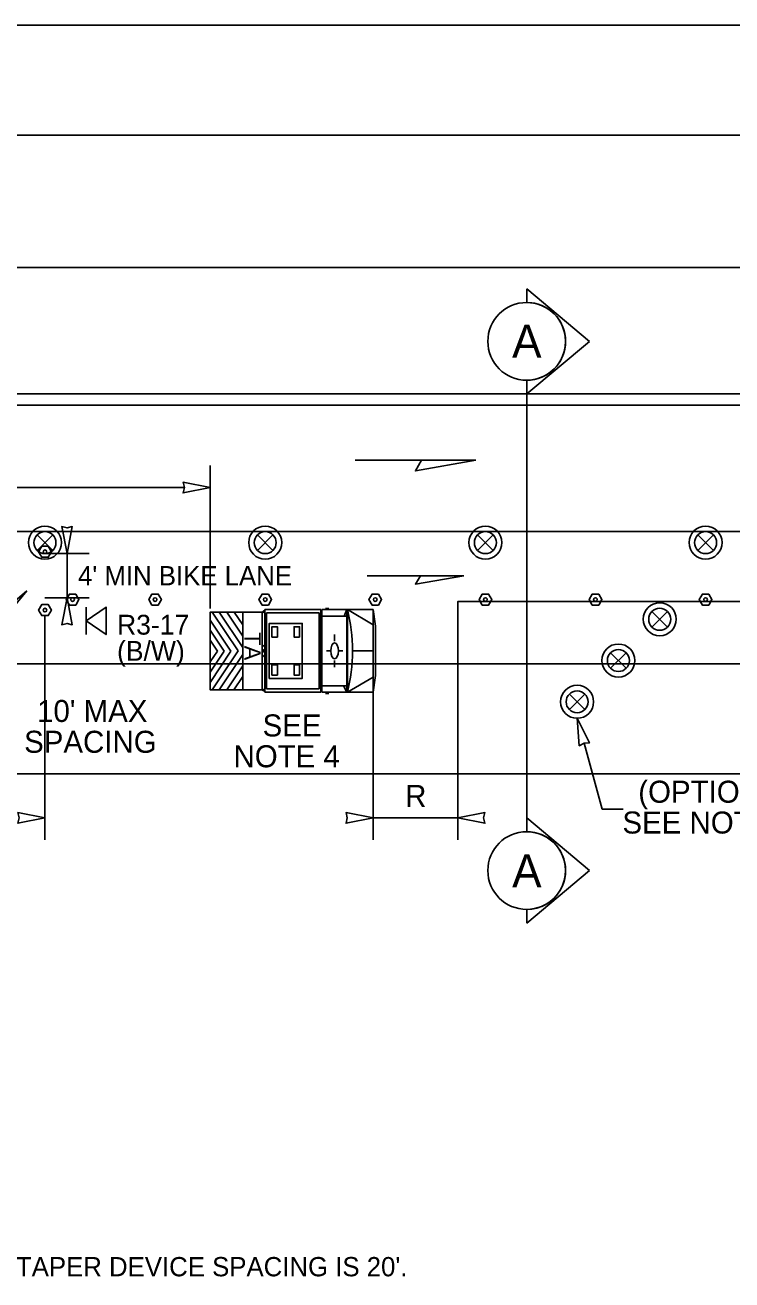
# Model space of a CAD drawing. Extents: x 99958 to 100176, y 99935 to 100011.
# Drawn here: x 100008.891 to 100011.459, y 99942.898 to 99947.456 of the extents above; entities that cross this region are included whole.
import ezdxf

# ---------------------------------------------------------------- set-up
doc = ezdxf.new("R2010")
doc.units = 0
for name, color, linetype in [('RD_ED_ShoulderPavedEdge', 7, 'Continuous'), ('RD_MK_LineDblYellowCenter', 7, 'Continuous'), ('RD_MK_LineEdgeWhite', 7, 'Continuous'), ('RD_MK_LineLane', 7, 'Continuous'), ('SH_GI_GeneralNotesBodyText', 7, 'Continuous'), ('SH_TI_WZSectionCut', 7, 'Continuous'), ('TR_SN_ConstructionSigns', 7, 'Continuous'), ('TR_WZ_PortableSignMountBlk-Wht', 7, 'Continuous'), ('TR_WZ_TrafficSafetyDrum', 7, 'Continuous'), ('TR_WZ_TransportableAttenuator', 7, 'Continuous'), ('TR_WZ_TubularMarker', 7, 'Continuous'), ('TR_WZ_WorkZoneDetails', 7, 'Continuous'), ('TR_WZ_WorkZoneTextCurrent', 7, 'Continuous')]:
    doc.layers.add(name, color=color, linetype=linetype)

msp = doc.modelspace()

# ---------------------------------------------------------------- linework, layer by layer
at = {"layer": 'RD_ED_ShoulderPavedEdge'}
for p, q in [((100000.8283, 99947.4557), (100014.8933, 99947.4557)), ((100000.8283, 99944.7357), (100014.8933, 99944.7357))]:
    msp.add_line(p, q, dxfattribs=at)
at = {"layer": 'RD_MK_LineDblYellowCenter'}
for p, q in [((100000.8283, 99946.1157), (100014.914, 99946.1157)), ((100000.8283, 99946.0757), (100014.8726, 99946.0757))]:
    msp.add_line(p, q, dxfattribs=at)
at = {"layer": 'RD_MK_LineEdgeWhite'}
for p, q in [((100000.8283, 99947.0557), (100014.8933, 99947.0557)), ((100000.8283, 99945.1357), (100014.8933, 99945.1357))]:
    msp.add_line(p, q, dxfattribs=at)
at = {"layer": 'RD_MK_LineLane'}
for points in [[(100014.8933, 99946.5757), (100000.8283, 99946.5757)], [(100014.8933, 99945.6157), (100000.8283, 99945.6157)]]:
    msp.add_lwpolyline(points, dxfattribs=at)
at = {"layer": 'SH_TI_WZSectionCut'}
for p, q in [((100010.7136, 99946.4481), (100010.7136, 99946.498)), ((100010.7136, 99946.498), (100010.9417, 99946.3069)), ((100010.9417, 99946.3069), (100010.7136, 99946.1157)), ((100010.7136, 99946.1157), (100010.7136, 99946.1656)), ((100010.7136, 99946.1157), (100010.7136, 99944.5757)), ((100010.7136, 99944.5757), (100010.7136, 99944.5258)), ((100010.9417, 99944.3846), (100010.7136, 99944.5757)), ((100010.7136, 99944.1935), (100010.9417, 99944.3846)), ((100010.7136, 99944.2434), (100010.7136, 99944.1935))]:
    msp.add_line(p, q, dxfattribs=at)
for centre in [(100010.7136, 99946.3069), (100010.7136, 99944.3846)]:
    msp.add_circle(centre, 0.1412, dxfattribs=at)
for centre in [(100010.7136, 99946.3069), (100010.7136, 99944.3846)]:
    msp.add_arc(centre, 0.1412, 269.9978, 90.0022, dxfattribs=at)
at = {"layer": 'TR_WZ_PortableSignMountBlk-Wht'}
msp.add_line((100009.1136, 99945.2416), (100009.1136, 99945.3416), dxfattribs=at)
msp.add_lwpolyline([(100009.1136, 99945.2916), (100009.1854, 99945.3416), (100009.1854, 99945.2416)], close=True, dxfattribs=at)
at = {"layer": 'TR_WZ_TrafficSafetyDrum'}
for p, q in [((100008.9353, 99945.604), (100008.9919, 99945.5474)), ((100008.9919, 99945.604), (100008.9353, 99945.5474)), ((100008.9353, 99945.604), (100008.9919, 99945.5474)), ((100008.9919, 99945.604), (100008.9353, 99945.5474)), ((100009.7353, 99945.604), (100009.7919, 99945.5474)), ((100009.7919, 99945.604), (100009.7353, 99945.5474)), ((100009.7353, 99945.604), (100009.7919, 99945.5474)), ((100009.7919, 99945.604), (100009.7353, 99945.5474)), ((100010.5353, 99945.604), (100010.5919, 99945.5474)), ((100010.5919, 99945.604), (100010.5353, 99945.5474)), ((100010.5353, 99945.604), (100010.5919, 99945.5474)), ((100010.5919, 99945.604), (100010.5353, 99945.5474)), ((100011.3353, 99945.604), (100011.3919, 99945.5474)), ((100011.3919, 99945.604), (100011.3353, 99945.5474)), ((100011.3353, 99945.604), (100011.3919, 99945.5474)), ((100011.3919, 99945.604), (100011.3353, 99945.5474)), ((100011.2252, 99945.2692), (100011.1686, 99945.3257)), ((100011.1686, 99945.2692), (100011.2252, 99945.3257)), ((100011.0752, 99945.1192), (100011.0186, 99945.1757)), ((100011.0186, 99945.1192), (100011.0752, 99945.1757)), ((100010.9252, 99944.9692), (100010.8686, 99945.0257)), ((100010.8686, 99944.9692), (100010.9252, 99945.0257))]:
    msp.add_line(p, q, dxfattribs=at)
for centre, radius in [((100008.9636, 99945.5757), 0.06), ((100008.9636, 99945.5757), 0.06), ((100008.9636, 99945.5757), 0.06), ((100008.9636, 99945.5757), 0.06), ((100008.9636, 99945.5757), 0.04), ((100008.9636, 99945.5757), 0.04), ((100009.7636, 99945.5757), 0.06), ((100009.7636, 99945.5757), 0.06), ((100009.7636, 99945.5757), 0.06), ((100009.7636, 99945.5757), 0.06), ((100009.7636, 99945.5757), 0.04), ((100009.7636, 99945.5757), 0.04), ((100010.5636, 99945.5757), 0.06), ((100010.5636, 99945.5757), 0.06), ((100010.5636, 99945.5757), 0.06), ((100010.5636, 99945.5757), 0.06), ((100010.5636, 99945.5757), 0.04), ((100010.5636, 99945.5757), 0.04), ((100011.3636, 99945.5757), 0.06), ((100011.3636, 99945.5757), 0.06), ((100011.3636, 99945.5757), 0.06), ((100011.3636, 99945.5757), 0.06), ((100011.3636, 99945.5757), 0.04), ((100011.3636, 99945.5757), 0.04), ((100011.1969, 99945.2975), 0.06), ((100011.1969, 99945.2975), 0.06), ((100011.1969, 99945.2975), 0.04), ((100011.0469, 99945.1475), 0.06), ((100011.0469, 99945.1475), 0.06), ((100011.0469, 99945.1475), 0.04), ((100010.8969, 99944.9975), 0.06), ((100010.8969, 99944.9975), 0.06), ((100010.8969, 99944.9975), 0.04)]:
    msp.add_circle(centre, radius, dxfattribs=at)
at = {"layer": 'TR_WZ_TransportableAttenuator'}
for p, q in [((100009.5965, 99945.3231), (100009.5713, 99945.3231)), ((100009.5713, 99945.3231), (100009.6651, 99945.1821)), ((100009.6651, 99945.1821), (100009.5713, 99945.3231)), ((100009.5713, 99945.3231), (100009.5965, 99945.3231)), ((100009.6818, 99945.1948), (100009.5965, 99945.3231)), ((100009.5965, 99945.3231), (100009.6818, 99945.1948)), ((100009.651, 99945.3231), (100009.624, 99945.3231)), ((100009.624, 99945.3231), (100009.6818, 99945.2363)), ((100009.6818, 99945.2363), (100009.624, 99945.3231)), ((100009.624, 99945.3231), (100009.651, 99945.3231)), ((100009.6818, 99945.2777), (100009.651, 99945.3231)), ((100009.651, 99945.3231), (100009.6818, 99945.2777)), ((100009.7625, 99945.3229), (100009.6818, 99945.3229)), ((100009.6818, 99945.3229), (100009.6818, 99945.0413)), ((100009.7529, 99945.0465), (100009.7529, 99945.3183)), ((100009.7574, 99945.3275), (100009.7618, 99945.3275)), ((100009.7618, 99945.0373), (100009.7618, 99945.3275)), ((100009.7625, 99945.3324), (100009.966, 99945.3324)), ((100009.7625, 99945.0324), (100009.7625, 99945.3324)), ((100009.7625, 99945.0418), (100009.7625, 99945.3229)), ((100009.7683, 99945.0444), (100009.7683, 99945.3204)), ((100009.7683, 99945.3204), (100009.9603, 99945.3204)), ((100009.9603, 99945.0444), (100009.9603, 99945.3204)), ((100009.966, 99945.0324), (100009.966, 99945.3324)), ((100009.9688, 99945.0324), (100009.9688, 99945.3324)), ((100010.1557, 99945.3324), (100009.9688, 99945.3324)), ((100009.9943, 99945.3366), (100009.983, 99945.3366)), ((100010.0507, 99945.3092), (100010.0606, 99945.3324)), ((100010.0606, 99945.0324), (100010.0606, 99945.3324)), ((100010.0622, 99945.0324), (100010.0622, 99945.3324)), ((100010.1557, 99945.2775), (100010.0622, 99945.3324)), ((100010.1557, 99945.0324), (100010.1557, 99945.3324)), ((100010.1557, 99945.3324), (100010.1649, 99945.2718)), ((100009.6389, 99945.1813), (100009.5636, 99945.2945)), ((100009.5636, 99945.2945), (100009.5636, 99945.2577)), ((100009.5636, 99945.2577), (100009.5636, 99945.2945)), ((100009.5636, 99945.2945), (100009.6389, 99945.1813)), ((100009.6818, 99945.2363), (100009.6818, 99945.2777)), ((100009.6818, 99945.2777), (100009.6818, 99945.2363)), ((100010.0606, 99945.3092), (100009.9688, 99945.3092)), ((100010.1649, 99945.093), (100010.1649, 99945.2718)), ((100009.5636, 99945.2577), (100009.6147, 99945.1809)), ((100009.6147, 99945.1809), (100009.5636, 99945.2577)), ((100010.0157, 99945.2419), (100010.0157, 99945.2176)), ((100009.5898, 99945.182), (100009.5636, 99945.2212)), ((100009.5636, 99945.2212), (100009.5636, 99945.1432)), ((100009.5636, 99945.2212), (100009.5898, 99945.182)), ((100009.5636, 99945.1432), (100009.5636, 99945.2212)), ((100009.5636, 99945.1432), (100009.5898, 99945.182)), ((100009.5898, 99945.182), (100009.5636, 99945.1432)), ((100009.5636, 99945.0681), (100009.6389, 99945.1813)), ((100009.6389, 99945.1813), (100009.5636, 99945.0681)), ((100009.6147, 99945.1809), (100009.5636, 99945.1046)), ((100009.5636, 99945.1046), (100009.6147, 99945.1809)), ((100009.6651, 99945.1821), (100009.5714, 99945.0413)), ((100009.5714, 99945.0413), (100009.6651, 99945.1821)), ((100009.6818, 99945.1697), (100009.6818, 99945.1948)), ((100009.6818, 99945.1948), (100009.6818, 99945.1697)), ((100009.7529, 99945.2036), (100009.7618, 99945.1979)), ((100009.7553, 99945.1824), (100009.7594, 99945.1824)), ((100009.7574, 99945.1782), (100009.7574, 99945.1866)), ((100009.9858, 99945.1822), (100009.9983, 99945.1823)), ((100010.0017, 99945.1829), (100010.0017, 99945.1829)), ((100010.0455, 99945.1822), (100010.033, 99945.1823)), ((100010.1557, 99945.1824), (100010.0806, 99945.1824)), ((100009.597, 99945.0413), (100009.6818, 99945.1697)), ((100009.6818, 99945.1697), (100009.597, 99945.0413)), ((100009.7529, 99945.1613), (100009.7618, 99945.1669)), ((100010.0157, 99945.123), (100010.0157, 99945.1472)), ((100009.5636, 99945.1046), (100009.5636, 99945.0681)), ((100009.5636, 99945.0681), (100009.5636, 99945.1046)), ((100009.6818, 99945.1282), (100009.6247, 99945.0413)), ((100009.6247, 99945.0413), (100009.6818, 99945.1282)), ((100009.6502, 99945.0413), (100009.6818, 99945.089)), ((100009.6818, 99945.089), (100009.6502, 99945.0413)), ((100009.6818, 99945.089), (100009.6818, 99945.1282)), ((100009.6818, 99945.1282), (100009.6818, 99945.089)), ((100010.1557, 99945.0324), (100010.1649, 99945.093)), ((100009.7683, 99945.0444), (100009.9603, 99945.0444)), ((100010.0606, 99945.0557), (100009.9688, 99945.0557)), ((100010.0606, 99945.0324), (100010.0486, 99945.0557)), ((100010.1557, 99945.0874), (100010.0622, 99945.0324)), ((100009.5714, 99945.0413), (100009.597, 99945.0413)), ((100009.597, 99945.0413), (100009.5714, 99945.0413)), ((100009.6247, 99945.0413), (100009.6502, 99945.0413)), ((100009.6502, 99945.0413), (100009.6247, 99945.0413)), ((100009.7625, 99945.0413), (100009.6818, 99945.0413)), ((100009.7574, 99945.0373), (100009.7618, 99945.0373)), ((100009.7625, 99945.0324), (100009.966, 99945.0324)), ((100010.1557, 99945.0324), (100009.9688, 99945.0324)), ((100009.9943, 99945.0282), (100009.983, 99945.0282))]:
    msp.add_line(p, q, dxfattribs=at)
for points in [[(100009.6818, 99945.3231), (100009.5636, 99945.3231), (100009.5636, 99945.0413), (100009.6818, 99945.0413)], [(100009.7783, 99945.0824), (100009.8985, 99945.0824), (100009.8985, 99945.2824), (100009.7783, 99945.2824)], [(100009.7883, 99945.2324), (100009.8083, 99945.2324), (100009.8083, 99945.2699), (100009.7883, 99945.2699)], [(100009.8885, 99945.2324), (100009.8685, 99945.2324), (100009.8685, 99945.2699), (100009.8885, 99945.2699)], [(100009.7883, 99945.0949), (100009.8083, 99945.0949), (100009.8083, 99945.1324), (100009.7883, 99945.1324)], [(100009.8885, 99945.0949), (100009.8685, 99945.0949), (100009.8685, 99945.1324), (100009.8885, 99945.1324)]]:
    msp.add_lwpolyline(points, close=True, dxfattribs=at)
msp.add_lwpolyline([(100009.6818, 99945.0413), (100009.5636, 99945.0413), (100009.5636, 99945.3231), (100009.6818, 99945.3229)], dxfattribs=at)
for centre, major_axis, start_param, end_param in [((100009.7574, 99945.3183), (0, 0.00916), 0, 1.570796), ((100009.9287, 99945.1824), (0, 0.3148), 4.215667, 5.208926), ((100009.7574, 99945.0465), (0, -0.00916), 4.712389, 6.283185)]:
    msp.add_ellipse(centre, major_axis=major_axis, ratio=0.482618, start_param=start_param, end_param=end_param, dxfattribs=at)
for centre, major_axis in [((100009.7574, 99945.1824), (0, -0.00423)), ((100010.0157, 99945.1824), (0, -0.0289))]:
    msp.add_ellipse(centre, major_axis=major_axis, ratio=0.482618, dxfattribs=at)
at = {"layer": 'TR_WZ_TubularMarker'}
for points in [[(100008.9405, 99945.5424), (100008.9521, 99945.5624), (100008.9752, 99945.5624), (100008.9867, 99945.5424), (100008.9752, 99945.5224), (100008.9521, 99945.5224)], [(100009.0405, 99945.3691), (100009.0521, 99945.3891), (100009.0752, 99945.3891), (100009.0867, 99945.3691), (100009.0752, 99945.3491), (100009.0521, 99945.3491)], [(100009.3405, 99945.3691), (100009.3521, 99945.3891), (100009.3752, 99945.3891), (100009.3867, 99945.3691), (100009.3752, 99945.3491), (100009.3521, 99945.3491)], [(100009.7405, 99945.3691), (100009.7521, 99945.3891), (100009.7752, 99945.3891), (100009.7867, 99945.3691), (100009.7752, 99945.3491), (100009.7521, 99945.3491)], [(100010.1405, 99945.3691), (100010.1521, 99945.3891), (100010.1752, 99945.3891), (100010.1867, 99945.3691), (100010.1752, 99945.3491), (100010.1521, 99945.3491)], [(100010.5405, 99945.3691), (100010.5521, 99945.3891), (100010.5752, 99945.3891), (100010.5867, 99945.3691), (100010.5752, 99945.3491), (100010.5521, 99945.3491)], [(100010.9405, 99945.3691), (100010.9521, 99945.3891), (100010.9752, 99945.3891), (100010.9867, 99945.3691), (100010.9752, 99945.3491), (100010.9521, 99945.3491)], [(100011.3405, 99945.3691), (100011.3521, 99945.3891), (100011.3752, 99945.3891), (100011.3867, 99945.3691), (100011.3752, 99945.3491), (100011.3521, 99945.3491)], [(100008.9405, 99945.3308), (100008.9521, 99945.3508), (100008.9752, 99945.3508), (100008.9867, 99945.3308), (100008.9752, 99945.3108), (100008.9521, 99945.3108)]]:
    msp.add_lwpolyline(points, close=True, dxfattribs=at)
for points in [[(100008.9521, 99945.5224), (100008.9752, 99945.5224), (100008.9867, 99945.5424), (100008.9752, 99945.5624), (100008.9521, 99945.5624), (100008.9405, 99945.5424), (100008.9521, 99945.5224)], [(100009.0521, 99945.3491), (100009.0752, 99945.3491), (100009.0867, 99945.3691), (100009.0752, 99945.3891), (100009.0521, 99945.3891), (100009.0405, 99945.3691), (100009.0521, 99945.3491)], [(100009.3521, 99945.3491), (100009.3752, 99945.3491), (100009.3867, 99945.3691), (100009.3752, 99945.3891), (100009.3521, 99945.3891), (100009.3405, 99945.3691), (100009.3521, 99945.3491)], [(100009.7521, 99945.3491), (100009.7752, 99945.3491), (100009.7867, 99945.3691), (100009.7752, 99945.3891), (100009.7521, 99945.3891), (100009.7405, 99945.3691), (100009.7521, 99945.3491)], [(100010.1521, 99945.3491), (100010.1752, 99945.3491), (100010.1867, 99945.3691), (100010.1752, 99945.3891), (100010.1521, 99945.3891), (100010.1405, 99945.3691), (100010.1521, 99945.3491)], [(100010.5521, 99945.3491), (100010.5752, 99945.3491), (100010.5867, 99945.3691), (100010.5752, 99945.3891), (100010.5521, 99945.3891), (100010.5405, 99945.3691), (100010.5521, 99945.3491)], [(100010.9521, 99945.3491), (100010.9752, 99945.3491), (100010.9867, 99945.3691), (100010.9752, 99945.3891), (100010.9521, 99945.3891), (100010.9405, 99945.3691), (100010.9521, 99945.3491)], [(100011.3521, 99945.3491), (100011.3752, 99945.3491), (100011.3867, 99945.3691), (100011.3752, 99945.3891), (100011.3521, 99945.3891), (100011.3405, 99945.3691), (100011.3521, 99945.3491)], [(100008.9521, 99945.3108), (100008.9752, 99945.3108), (100008.9867, 99945.3308), (100008.9752, 99945.3508), (100008.9521, 99945.3508), (100008.9405, 99945.3308), (100008.9521, 99945.3108)]]:
    msp.add_lwpolyline(points, dxfattribs=at)
for centre in [(100008.9636, 99945.5424), (100009.0636, 99945.3691), (100009.3636, 99945.3691), (100009.7636, 99945.3691), (100010.1636, 99945.3691), (100010.5636, 99945.3691), (100010.9636, 99945.3691), (100011.3636, 99945.3691), (100008.9636, 99945.3308)]:
    msp.add_circle(centre, 0.00667, dxfattribs=at)
at = {"layer": 'TR_WZ_WorkZoneDetails'}
for p, q in [((100010.3319, 99945.875), (100010.0908, 99945.875)), ((100009.5636, 99945.8557), (100009.5636, 99945.3362)), ((100009.4699, 99945.7757), (100006.6573, 99945.7757)), ((100009.1236, 99945.5357), (100008.9636, 99945.5357)), ((100009.0436, 99945.3757), (100009.0436, 99945.5357)), ((100010.3275, 99945.4557), (100010.1346, 99945.4557)), ((100009.1236, 99945.3757), (100008.9636, 99945.3757)), ((100008.9636, 99945.3108), (100008.9636, 99945.1357)), ((100008.9636, 99945.1357), (100008.9636, 99944.7357)), ((100010.1557, 99945.0324), (100010.1557, 99944.4957)), ((100010.9219, 99944.8471), (100010.9884, 99944.607)), ((100008.9636, 99944.7357), (100008.9636, 99944.4957)), ((100010.4636, 99944.7357), (100010.4636, 99944.4957)), ((100011.0647, 99944.607), (100010.9884, 99944.607)), ((100010.4636, 99944.5757), (100010.1557, 99944.5757))]:
    msp.add_line(p, q, dxfattribs=at)
for points in [[(100010.5285, 99945.875), (100010.3096, 99945.8364), (100010.3319, 99945.875)], [(100009.5636, 99945.7757), (100009.4653, 99945.795), (100009.4699, 99945.7757), (100009.4653, 99945.7565)], [(100009.0436, 99945.5357), (100009.0629, 99945.634), (100009.0436, 99945.6295), (100009.0243, 99945.634)], [(100010.4847, 99945.4557), (100010.3096, 99945.4249), (100010.3275, 99945.4557)], [(100008.8977, 99945.4008), (100008.7841, 99945.2641), (100008.7778, 99945.2992)], [(100009.0436, 99945.3757), (100009.0629, 99945.2774), (100009.0436, 99945.282), (100009.0243, 99945.2774)], [(100010.4636, 99944.7357), (100010.4636, 99945.3624), (100012.1636, 99945.3624), (100012.1636, 99944.7357)], [(100010.8969, 99944.9375), (100010.9417, 99944.8479), (100010.9219, 99944.8471), (100010.9045, 99944.8376)], [(100008.9636, 99944.5757), (100008.8653, 99944.595), (100008.8699, 99944.5757), (100008.8653, 99944.5565)], [(100010.1557, 99944.5757), (100010.0574, 99944.595), (100010.062, 99944.5757), (100010.0574, 99944.5565)], [(100010.4636, 99944.5757), (100010.5619, 99944.595), (100010.5573, 99944.5757), (100010.5619, 99944.5565)]]:
    msp.add_lwpolyline(points, close=True, dxfattribs=at)

# ---------------------------------------------------------------- texts
at = {"layer": 'SH_GI_GeneralNotesBodyText'}
msp.add_text("6. IF USED, DOWNSTREAM TAPER DEVICE SPACING IS 20'.", height=0.07, rotation=360, dxfattribs=at).set_placement((100007.6204, 99942.9106))
at = {"layer": 'SH_TI_WZSectionCut'}
for rotation, p in [(359.99, (100010.6606, 99946.2477)), (0.01, (100010.6607, 99944.3237))]:
    msp.add_text('A', height=0.12, rotation=rotation, dxfattribs=at).set_placement(p)
at = {"layer": 'TR_SN_ConstructionSigns'}
for s, p in [('R3-17', (100009.2254, 99945.2416)), ('(B/W)', (100009.2254, 99945.1466))]:
    msp.add_text(s, height=0.072, rotation=360, dxfattribs=at).set_placement(p)
at = {"layer": 'TR_WZ_TransportableAttenuator'}
msp.add_text('TA', height=0.06013, rotation=270, dxfattribs=at).set_placement((100009.6873, 99945.251))
at = {"layer": 'TR_WZ_WorkZoneTextCurrent'}
for s, height, p in [("4' MIN BIKE LANE", 0.07, (100009.0836, 99945.4207)), ("10' MAX", 0.08, (100008.9349, 99944.9243)), ('SEE', 0.08, (100009.7541, 99944.8717)), ('SPACING', 0.08, (100008.8878, 99944.8123)), ('NOTE 4', 0.08, (100009.6485, 99944.7597)), ('R', 0.08, (100010.2721, 99944.6157)), ('(OPTIONAL)', 0.08, (100011.119, 99944.631)), ('SEE NOTE 5', 0.08, (100011.0614, 99944.519))]:
    msp.add_text(s, height=height, dxfattribs=at).set_placement(p)

doc.saveas('drawing.dxf')
